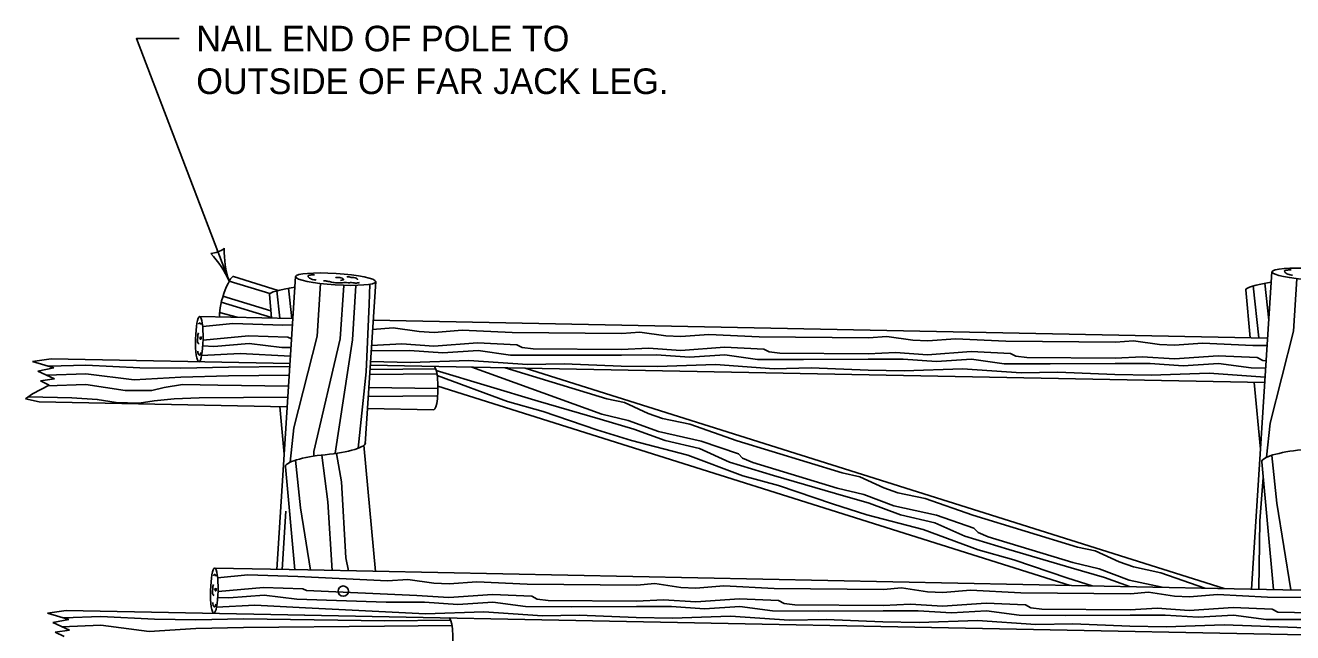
# Model space of a CAD drawing. Extents: x 49991.4 to 50021, y 49987.6 to 50011.4.
# Drawn here: x 50009.113 to 50012.08, y 49991.893 to 49993.316 of the extents above; entities that cross this region are included whole.
import ezdxf

# ---------------------------------------------------------------- set-up
doc = ezdxf.new("R2010")
doc.units = 0
for name, color, linetype in [('Level 1', 7, 'Continuous'), ('Level 2', 7, 'Continuous'), ('Level 3', 7, 'Continuous')]:
    doc.layers.add(name, color=color, linetype=linetype)

msp = doc.modelspace()

# ---------------------------------------------------------------- linework, layer by layer
at = {"layer": 'Level 1'}
for p, q in [((50009.7045, 49992.6947), (50009.6006, 49992.7274)), ((50009.7456, 49992.7271), (50009.7015, 49992.0416)), ((50012.0317, 49992.7385), (50011.9839, 49991.9954)), ((50009.9332, 49992.7154), (50009.9085, 49992.3356)), ((50009.6842, 49992.685), (50009.6892, 49992.6303)), ((50011.9703, 49992.6963), (50011.9807, 49992.5838)), ((50009.5213, 49992.6337), (50009.7394, 49992.6293)), ((50009.9274, 49992.6255), (50012.0217, 49992.583)), ((50009.1736, 49992.5346), (50009.13, 49992.5285)), ((50009.13, 49992.5285), (50009.1799, 49992.5136)), ((50009.1736, 49992.5346), (50009.7326, 49992.5236)), ((50009.9205, 49992.5199), (50012.015, 49992.4789)), ((50009.1799, 49992.5136), (50009.1422, 49992.5061)), ((50009.1422, 49992.5061), (50009.1815, 49992.4882)), ((50011.9201, 49991.9967), (50010.2831, 49992.5128)), ((50009.1689, 49992.4733), (50009.1296, 49992.4524)), ((50009.1815, 49992.4882), (50009.148, 49992.4835)), ((50009.148, 49992.4835), (50009.1689, 49992.4733)), ((50011.5594, 49992.004), (50010.0789, 49992.4708)), ((50011.9904, 49992.4794), (50012.0049, 49992.3232)), ((50009.1129, 49992.4406), (50009.1296, 49992.4524)), ((50009.1456, 49992.4336), (50009.1129, 49992.4406)), ((50009.1456, 49992.4336), (50009.726, 49992.4223)), ((50009.7085, 49992.4227), (50009.7189, 49992.3115)), ((50009.9139, 49992.4186), (50010.0694, 49992.4156)), ((50009.9057, 49992.3322), (50009.9331, 49992.0369)), ((50009.7217, 49992.282), (50009.7441, 49992.0408)), ((50012.0078, 49992.2934), (50012.0356, 49991.9943)), ((50009.5564, 49992.0446), (50009.7744, 49992.0402)), ((50009.7744, 49992.0402), (50012.0568, 49991.9939)), ((50012.0568, 49991.9939), (50014.3621, 49991.9472)), ((50009.2086, 49991.9454), (50009.165, 49991.9394)), ((50009.165, 49991.9394), (50009.2149, 49991.9245)), ((50009.2086, 49991.9454), (50009.7676, 49991.9345)), ((50009.7667, 49991.9345), (50012.238, 49991.8861)), ((50009.2149, 49991.9245), (50009.1773, 49991.917)), ((50009.1773, 49991.917), (50009.2165, 49991.8991)), ((50009.2165, 49991.8991), (50009.183, 49991.8944)), ((50009.183, 49991.8944), (50009.204, 49991.8841))]:
    msp.add_line(p, q, dxfattribs=at)
for points in [[(50009.6855, 49992.6873), (50009.59, 49992.7164)], [(50009.7367, 49992.6293), (50009.729, 49992.7001)], [(50009.7332, 49992.2927), (50009.7413, 49992.3729), (50009.7963, 49992.588), (50009.8041, 49992.7108)], [(50009.7881, 49992.3075), (50009.7885, 49992.3176), (50009.8502, 49992.5816), (50009.8583, 49992.7065)], [(50009.8381, 49992.3135), (50009.8787, 49992.5788), (50009.8869, 49992.7067)], [(50009.8925, 49992.3254), (50009.9107, 49992.5045), (50009.9176, 49992.6629), (50009.9193, 49992.7093)], [(50012.0013, 49992.5835), (50011.988, 49992.7054)], [(50012.0244, 49992.6255), (50012.0151, 49992.7115)], [(50012.0193, 49992.3041), (50012.0275, 49992.3843), (50012.0823, 49992.5994), (50012.0902, 49992.7222)], [(50009.6891, 49992.6314), (50009.5717, 49992.6671)], [(50009.6877, 49992.6472), (50009.5756, 49992.6813)], [(50009.7089, 49992.6299), (50009.702, 49992.694)], [(50009.6085, 49992.6319), (50009.5675, 49992.6432)], [(50009.7384, 49992.614), (50009.7161, 49992.6138), (50009.5985, 49992.6176), (50009.5281, 49992.6107)], [(50009.7362, 49992.5811), (50009.7275, 49992.5855), (50009.6355, 49992.5882), (50009.529, 49992.5787)], [(50010.5094, 49992.594), (50010.2528, 49992.5961), (50010.1353, 49992.602), (50010.07, 49992.5967), (50010.0346, 49992.5986), (50009.9738, 49992.6074), (50009.9259, 49992.6036)], [(50011.0873, 49992.5839), (50010.8307, 49992.586), (50010.7132, 49992.5919), (50010.6479, 49992.5866), (50010.6125, 49992.5885), (50010.5517, 49992.5973), (50010.5093, 49992.594)], [(50011.6652, 49992.5738), (50011.4087, 49992.5759), (50011.2911, 49992.5818), (50011.2259, 49992.5765), (50011.1905, 49992.5784), (50011.1297, 49992.5872), (50011.0873, 49992.5839)], [(50009.735, 49992.5614), (50009.7133, 49992.5611), (50009.6369, 49992.5704), (50009.5546, 49992.5637), (50009.5284, 49992.565)], [(50010.5085, 49992.5436), (50010.3568, 49992.5429), (50010.2491, 49992.5435), (50010.1728, 49992.554), (50010.0904, 49992.5488), (50010.0125, 49992.554), (50009.9227, 49992.5537)], [(50010.5087, 49992.5563), (50010.3018, 49992.5579), (50010.2763, 49992.561), (50010.2637, 49992.5676), (50010.1717, 49992.5719), (50010.0694, 49992.5646), (50009.9944, 49992.5697), (50009.9235, 49992.566)], [(50011.0866, 49992.5463), (50010.8797, 49992.5479), (50010.8542, 49992.5509), (50010.8416, 49992.5575), (50010.7497, 49992.5618), (50010.6473, 49992.5545), (50010.5723, 49992.5597), (50010.5087, 49992.5563)], [(50011.6646, 49992.5362), (50011.4576, 49992.5378), (50011.4322, 49992.5408), (50011.4195, 49992.5475), (50011.3276, 49992.5517), (50011.2253, 49992.5444), (50011.1503, 49992.5496), (50011.0866, 49992.5463)], [(50012.0206, 49992.5656), (50011.9866, 49992.5658), (50011.869, 49992.5717), (50011.8037, 49992.5664), (50011.7684, 49992.5683), (50011.7075, 49992.5771), (50011.6652, 49992.5738)], [(50009.7316, 49992.5165), (50009.5889, 49992.5151), (50009.4769, 49992.5125), (50009.3806, 49992.5138), (50009.2545, 49992.5202), (50009.1682, 49992.5171)], [(50009.7337, 49992.541), (50009.6155, 49992.547), (50009.5256, 49992.5424)], [(50010.508, 49992.5178), (50010.3748, 49992.5233), (50010.2884, 49992.5217), (50010.1511, 49992.531), (50010.0149, 49992.5264), (50009.921, 49992.5281)], [(50011.0859, 49992.5078), (50010.9528, 49992.5132), (50010.8663, 49992.5116), (50010.729, 49992.521), (50010.5928, 49992.5164), (50010.508, 49992.5178)], [(50011.0864, 49992.5335), (50010.9347, 49992.5328), (50010.827, 49992.5334), (50010.7507, 49992.5439), (50010.6683, 49992.5387), (50010.5905, 49992.5439), (50010.5085, 49992.5436)], [(50011.6643, 49992.5235), (50011.5126, 49992.5227), (50011.4049, 49992.5233), (50011.3286, 49992.5339), (50011.2463, 49992.5286), (50011.1684, 49992.5339), (50011.0864, 49992.5335)], [(50012.0172, 49992.513), (50011.9828, 49992.5132), (50011.9066, 49992.5238), (50011.8242, 49992.5186), (50011.7463, 49992.5238), (50011.6643, 49992.5235)], [(50012.0183, 49992.5298), (50012.0101, 49992.5307), (50011.9974, 49992.5374), (50011.9055, 49992.5416), (50011.8032, 49992.5344), (50011.7282, 49992.5395), (50011.6645, 49992.5362)], [(50009.7308, 49992.4961), (50009.5889, 49992.4947), (50009.4769, 49992.4921), (50009.3676, 49992.4852), (50009.2545, 49992.4998), (50009.1634, 49992.4965)], [(50010.0766, 49992.4995), (50009.919, 49992.4979)], [(50010.0737, 49992.5116), (50009.9198, 49992.51)], [(50010.4589, 49992.3932), (50010.3133, 49992.4356), (50010.0749, 49992.5077)], [(50010.4511, 49992.3686), (50010.3251, 49992.4117), (50010.2416, 49992.4346), (50010.0771, 49992.496)], [(50010.4627, 49992.4054), (50010.1583, 49992.5153)], [(50010.474, 49992.4413), (50010.2364, 49992.5137)], [(50011.6639, 49992.4977), (50011.5307, 49992.5032), (50011.4442, 49992.5015), (50011.3069, 49992.5109), (50011.1707, 49992.5063), (50011.0859, 49992.5078)], [(50012.0159, 49992.4919), (50011.8848, 49992.5008), (50011.7486, 49992.4962), (50011.6639, 49992.4977)], [(50009.7292, 49992.4707), (50009.5634, 49992.4732), (50009.4812, 49992.4745), (50009.438, 49992.4678), (50009.4093, 49992.4606), (50009.3469, 49992.4606), (50009.2545, 49992.4744), (50009.1649, 49992.4711)], [(50010.0789, 49992.4654), (50009.9171, 49992.4678)], [(50009.7275, 49992.4452), (50009.5195, 49992.4437), (50009.4614, 49992.4411), (50009.4146, 49992.436), (50009.3792, 49992.4309), (50009.3253, 49992.4321), (50009.2814, 49992.4398), (50009.2219, 49992.4437), (50009.1205, 49992.4459)], [(50010.0782, 49992.4477), (50009.9157, 49992.4465)], [(50011.0253, 49992.2674), (50010.7799, 49992.3423), (50010.6689, 49992.3813), (50010.6047, 49992.3949), (50010.5714, 49992.4068), (50010.5156, 49992.4324), (50010.474, 49992.4413)], [(50011.0139, 49992.2315), (50010.816, 49992.2919), (50010.7924, 49992.302), (50010.7823, 49992.312), (50010.6953, 49992.3422), (50010.5951, 49992.3642), (50010.5246, 49992.3905), (50010.4627, 49992.4054)], [(50011.01, 49992.2194), (50010.8645, 49992.2618), (50010.7614, 49992.293), (50010.6913, 49992.3247), (50010.6108, 49992.3432), (50010.5377, 49992.3702), (50010.4589, 49992.3932)], [(50011.0024, 49992.1949), (50010.8762, 49992.2379), (50010.7929, 49992.2609), (50010.6638, 49992.3089), (50010.532, 49992.3432), (50010.4511, 49992.3686)], [(50009.8693, 49992.0382), (50009.8633, 49992.0684), (50009.8532, 49992.2468), (50009.8412, 49992.3133)], [(50009.7806, 49992.04), (50009.7572, 49992.1856), (50009.7451, 49992.2972)], [(50009.831, 49992.039), (50009.8215, 49992.1994), (50009.8072, 49992.3092)], [(50012.076, 49991.9935), (50012.0433, 49992.197), (50012.0312, 49992.3086)], [(50011.5765, 49992.0936), (50011.3311, 49992.1685), (50011.2201, 49992.2075), (50011.156, 49992.221), (50011.1226, 49992.2329), (50011.0667, 49992.2586), (50011.0253, 49992.2674)], [(50012.0032, 49992.155), (50012.0112, 49992.257)], [(50011.5652, 49992.0577), (50011.3672, 49992.1181), (50011.3436, 49992.1282), (50011.3335, 49992.1381), (50011.2465, 49992.1684), (50011.1463, 49992.1905), (50011.0759, 49992.2167), (50011.0139, 49992.2315)], [(50011.5536, 49992.0211), (50011.4275, 49992.0641), (50011.3441, 49992.087), (50011.2151, 49992.1351), (50011.0833, 49992.1693), (50011.0024, 49992.1949)], [(50011.5613, 49992.0455), (50011.4157, 49992.088), (50011.3126, 49992.1192), (50011.2425, 49992.1508), (50011.162, 49992.1693), (50011.0888, 49992.1965), (50011.01, 49992.2194)], [(50009.7141, 49992.0414), (50009.7228, 49992.1778)], [(50012.0009, 49991.995), (50012.0032, 49992.155)], [(50011.8742, 49991.9976), (50011.7713, 49992.0338), (50011.7073, 49992.0472), (50011.6737, 49992.0591), (50011.618, 49992.0848), (50011.5765, 49992.0936)], [(50011.698, 49992.0012), (50011.64, 49992.0227), (50011.5613, 49992.0455)], [(50011.7748, 49991.9996), (50011.6976, 49992.0166), (50011.6272, 49992.0429), (50011.5652, 49992.0577)], [(50009.9609, 49992.0145), (50009.7512, 49992.0247), (50009.6335, 49992.0285), (50009.5631, 49992.0216)], [(50010.5444, 49992.0049), (50010.2878, 49992.0069), (50010.1703, 49992.0128), (50010.105, 49992.0075), (50010.0696, 49992.0094), (50010.0088, 49992.0182), (50009.9609, 49992.0145)], [(50011.6111, 49992.0029), (50011.5536, 49992.0211)], [(50009.7713, 49991.992), (50009.7625, 49991.9964), (50009.6705, 49991.9991), (50009.5641, 49991.9896)], [(50010.5437, 49991.9672), (50010.3368, 49991.9688), (50010.3113, 49991.9719), (50010.2987, 49991.9785), (50010.2068, 49991.9827), (50010.1045, 49991.9755), (50010.0294, 49991.9806), (50009.7713, 49991.992)], [(50011.1223, 49991.9948), (50010.8658, 49991.9969), (50010.7482, 49992.0028), (50010.6829, 49991.9975), (50010.6475, 49991.9994), (50010.5867, 49992.0082), (50010.5444, 49992.0049)], [(50011.7003, 49991.9847), (50011.4437, 49991.9868), (50011.3262, 49991.9927), (50011.2609, 49991.9874), (50011.2255, 49991.9893), (50011.1647, 49991.9981), (50011.1223, 49991.9948)], [(50012.2437, 49991.9749), (50012.0216, 49991.9767), (50011.9041, 49991.9826), (50011.8388, 49991.9773), (50011.8034, 49991.9792), (50011.7426, 49991.988), (50011.7002, 49991.9847)], [(50009.7687, 49991.9519), (50009.6505, 49991.9579), (50009.5606, 49991.9533)], [(50009.9577, 49991.9645), (50009.7483, 49991.972), (50009.6719, 49991.9812), (50009.5896, 49991.9746), (50009.5634, 49991.9759)], [(50010.5435, 49991.9545), (50010.3918, 49991.9537), (50010.2841, 49991.9543), (50010.2078, 49991.9649), (50010.1255, 49991.9597), (50010.0476, 49991.9649), (50009.9577, 49991.9645)], [(50011.1217, 49991.9571), (50010.9147, 49991.9587), (50010.8893, 49991.9618), (50010.8766, 49991.9684), (50010.7847, 49991.9727), (50010.6824, 49991.9654), (50010.6073, 49991.9705), (50010.5437, 49991.9672)], [(50011.6996, 49991.9471), (50011.4927, 49991.9487), (50011.4672, 49991.9517), (50011.4546, 49991.9584), (50011.3627, 49991.9626), (50011.2603, 49991.9553), (50011.1853, 49991.9605), (50011.1217, 49991.9571)], [(50009.9549, 49991.9209), (50009.6239, 49991.926), (50009.512, 49991.9234), (50009.4156, 49991.9247), (50009.2895, 49991.9311), (50009.2032, 49991.928)], [(50010.543, 49991.9287), (50010.4099, 49991.9342), (50010.3234, 49991.9325), (50010.1861, 49991.9419), (50010.0499, 49991.9373), (50009.7687, 49991.9519)], [(50011.121, 49991.9186), (50010.9878, 49991.9241), (50010.9013, 49991.9225), (50010.764, 49991.9318), (50010.6278, 49991.9272), (50010.543, 49991.9287)], [(50011.1214, 49991.9444), (50010.9698, 49991.9437), (50010.862, 49991.9443), (50010.7858, 49991.9548), (50010.7034, 49991.9496), (50010.6255, 49991.9548), (50010.5435, 49991.9545)], [(50011.6994, 49991.9344), (50011.5477, 49991.9336), (50011.44, 49991.9342), (50011.3637, 49991.9448), (50011.2813, 49991.9395), (50011.2034, 49991.9448), (50011.1214, 49991.9444)], [(50012.0522, 49991.9239), (50012.0179, 49991.9241), (50011.9416, 49991.9347), (50011.8592, 49991.9294), (50011.7813, 49991.9347), (50011.6994, 49991.9344)], [(50012.2413, 49991.9373), (50012.0451, 49991.9416), (50012.0325, 49991.9483), (50011.9405, 49991.9525), (50011.8382, 49991.9452), (50011.7632, 49991.9504), (50011.6995, 49991.9471)], [(50009.9541, 49991.9088), (50009.6239, 49991.9056), (50009.512, 49991.903), (50009.4027, 49991.8961), (50009.2895, 49991.9107), (50009.1984, 49991.9074)], [(50010.1116, 49991.9104), (50009.9541, 49991.9088)], [(50010.1087, 49991.9224), (50009.9549, 49991.9209)], [(50011.6989, 49991.9086), (50011.5657, 49991.914), (50011.4792, 49991.9124), (50011.3419, 49991.9218), (50011.2057, 49991.9172), (50011.121, 49991.9186)], [(50012.2389, 49991.9), (50011.9199, 49991.9117), (50011.7837, 49991.9071), (50011.6989, 49991.9086)], [(50012.2773, 49991.9243), (50012.0522, 49991.9239)]]:
    msp.add_lwpolyline(points, dxfattribs=at)
msp.add_circle((50009.8573, 49991.9908), 0.012, dxfattribs=at)
for centre, major_axis, ratio, start_param, end_param in [((50009.5854, 49992.679), (0.0153, 0.0484), 0.196346, 0.001095, 2.897749), ((50009.7776, 49992.6947), (-0.0934, -0.0097), 0.126327, 5.066199, 6.283302), ((50012.0637, 49992.7061), (-0.0934, -0.0097), 0.126327, 5.066199, 6.283302), ((50010.0694, 49992.4664), (0, -0.0508), 0.187855, 6.283183, 9.424783), ((50009.8161, 49992.3293), (0.0932, 0.0089), 0.201992, 4.679863, 6.355951), ((50012.1013, 49992.3025), (0.0934, 0.0089), 0.201542, 1.555621, 3.157543), ((50009.8152, 49992.2911), (0.0934, 0.0089), 0.201542, 1.555621, 3.157543), ((50010.1044, 49991.8773), (0, -0.0508), 0.187855, 6.283183, 9.424783)]:
    msp.add_ellipse(centre, major_axis=major_axis, ratio=ratio, start_param=start_param, end_param=end_param, dxfattribs=at)
for centre, major_axis, ratio in [((50009.8395, 49992.7212), (0.0937, -0.0058), 0.143064), ((50012.1256, 49992.7326), (0.0937, -0.0058), 0.143064), ((50009.5202, 49992.5807), (0.0011, 0.053), 0.166587), ((50009.5553, 49991.9916), (0.0011, 0.053), 0.166587)]:
    msp.add_ellipse(centre, major_axis=major_axis, ratio=ratio, dxfattribs=at)
for points in [[(50009.7941, 49992.7188), (50009.7885, 49992.72), (50009.7828, 49992.7213), (50009.7784, 49992.7239), (50009.7754, 49992.7266), (50009.7759, 49992.7298), (50009.7799, 49992.7307), (50009.7843, 49992.7316), (50009.7903, 49992.7313)], [(50009.8654, 49992.7274), (50009.8678, 49992.7266), (50009.8712, 49992.7263), (50009.8755, 49992.7255), (50009.8795, 49992.7254), (50009.8848, 49992.7242), (50009.887, 49992.7239), (50009.8894, 49992.7225), (50009.8902, 49992.7211), (50009.8907, 49992.72), (50009.8907, 49992.7197)], [(50012.0802, 49992.7302), (50012.0746, 49992.7313), (50012.0689, 49992.7327), (50012.0646, 49992.7353), (50012.0615, 49992.738), (50012.0621, 49992.7412), (50012.066, 49992.7421), (50012.0704, 49992.743), (50012.0763, 49992.7427)], [(50009.811, 49992.7172), (50009.8163, 49992.7172), (50009.8192, 49992.7162), (50009.8251, 49992.7154), (50009.8299, 49992.7143), (50009.8357, 49992.7133), (50009.8422, 49992.7123), (50009.8458, 49992.7123), (50009.8554, 49992.7129), (50009.8555, 49992.7129), (50009.8615, 49992.7133), (50009.8689, 49992.7129), (50009.8795, 49992.7129), (50009.8855, 49992.7119), (50009.8907, 49992.7123), (50009.8955, 49992.7136)], [(50009.8511, 49992.7179), (50009.8566, 49992.7197), (50009.8581, 49992.72), (50009.8555, 49992.7228), (50009.8545, 49992.7234), (50009.8492, 49992.725), (50009.844, 49992.7255), (50009.8396, 49992.7255), (50009.8391, 49992.726)], [(50009.5237, 49992.6151), (50009.5233, 49992.6174), (50009.521, 49992.6188), (50009.5202, 49992.6185), (50009.5186, 49992.6159)], [(50009.5186, 49992.5953), (50009.517, 49992.5909), (50009.5166, 49992.5837), (50009.5174, 49992.5714), (50009.5198, 49992.5692)], [(50009.5225, 49992.5864), (50009.5229, 49992.5804), (50009.5245, 49992.5811), (50009.5245, 49992.5834), (50009.5253, 49992.5871)], [(50009.5166, 49992.5529), (50009.5173, 49992.5469), (50009.5189, 49992.5439), (50009.5209, 49992.5428), (50009.5213, 49992.5436), (50009.5244, 49992.5496)], [(50009.5587, 49992.026), (50009.5583, 49992.0282), (50009.556, 49992.0297), (50009.5552, 49992.0294), (50009.5536, 49992.0268)], [(50009.5536, 49992.0062), (50009.552, 49992.0017), (50009.5516, 49991.9946), (50009.5524, 49991.9823), (50009.5548, 49991.9801)], [(50009.5575, 49991.9973), (50009.5579, 49991.9913), (50009.5595, 49991.992), (50009.5595, 49991.9943), (50009.5603, 49991.998)], [(50009.5516, 49991.9638), (50009.5524, 49991.9578), (50009.5539, 49991.9548), (50009.5559, 49991.9537), (50009.5563, 49991.9545), (50009.5595, 49991.9605)]]:
    msp.add_spline(points, degree=3, dxfattribs=at)
at = {"layer": 'Level 3'}
msp.add_lwpolyline([(50009.473, 49993.2847), (50009.373, 49993.2847), (50009.59, 49992.7164)], dxfattribs=at)
for centre, radius, start, end in [((50009.5443, 49992.8362), 0.0548, 273.0433, 308.7657), ((50009.8008, 49992.7871), 0.2223, 178.3605, 198.544), ((50009.3767, 49992.6227), 0.233, 23.7318, 42.9816)]:
    msp.add_arc(centre, radius, start, end, dxfattribs=at)

# ---------------------------------------------------------------- texts
at = {"layer": 'Level 2'}
for s, p in [('NAIL END OF POLE TO', (50009.513, 49993.2547)), ('OUTSIDE OF FAR JACK LEG.', (50009.513, 49993.1547))]:
    msp.add_text(s, height=0.06, dxfattribs=at).set_placement(p)

doc.saveas('drawing.dxf')
